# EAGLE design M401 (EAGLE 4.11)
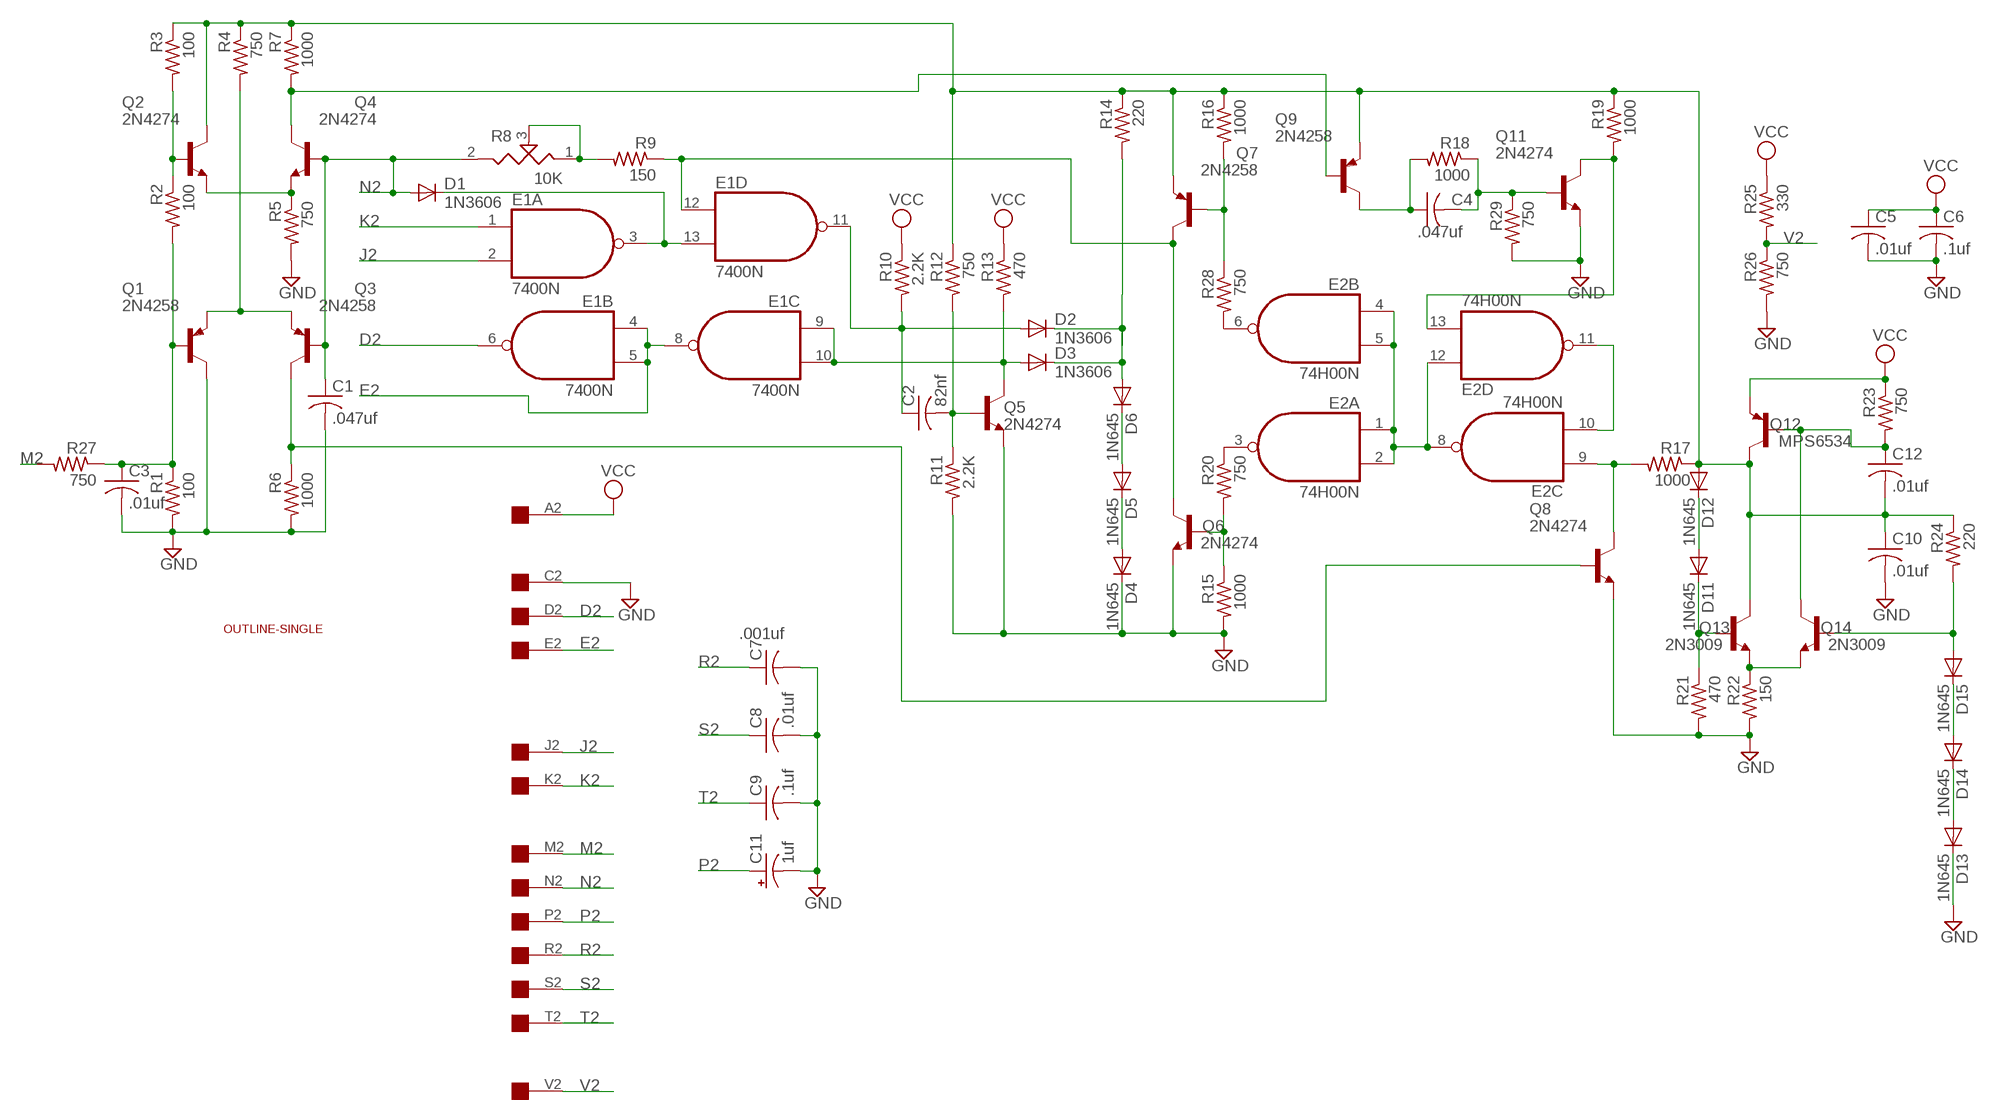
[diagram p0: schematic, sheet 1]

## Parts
C1  .047uf  C-US050-025X075  [C050-025X075]
C2  82nf  C-US050-025X075  [C050-025X075]
C3  .01uf  C-US050-025X075  [C050-025X075]
C4  .047uf  C-US050-025X075  [C050-025X075]
C5  .01uf  C-US050-025X075  [C050-025X075]
C6  .1uf  C-US050-025X075  [C050-025X075]
C7  .001uf  C-US050-025X075  [C050-025X075]
C8  .01uf  C-US050-025X075  [C050-025X075]
C9  .1uf  C-US050-025X075  [C050-025X075]
C10  .01uf  C-US050-025X075  [C050-025X075]
C11  1uf  CPOL-USE15-5AXIAL  [E15-5]
C12  .01uf  C-US050-025X075  [C050-025X075]
D1  1N3606  1N4148  [DO35-10]
D2  1N3606  1N4148  [DO35-10]
D3  1N3606  1N4148  [DO35-10]
D4  1N645  1N4148  [DO35-10]
D5  1N645  1N4148  [DO35-10]
D6  1N645  1N4148  [DO35-10]
D11  1N645  1N4148  [DO35-10]
D12  1N645  1N4148  [DO35-10]
D13  1N645  1N4148  [DO35-10]
D14  1N645  1N4148  [DO35-10]
D15  1N645  1N4148  [DO35-10]
E1  7400N  [DIL14]
E2  74H00N  7400N  [DIL14]
Q1  2N4258  2N3637-PNP-TO39-EBC  [TO39]
Q2  2N4274  2N3019-NPN-TO39-EBC  [TO39]
Q3  2N4258  2N3637-PNP-TO39-EBC  [TO39]
Q4  2N4274  2N3019-NPN-TO39-EBC  [TO39]
Q5  2N4274  2N3019-NPN-TO39-EBC  [TO39]
Q6  2N4274  2N3019-NPN-TO39-EBC  [TO39]
Q7  2N4258  2N3637-PNP-TO39-EBC  [TO39]
Q8  2N4274  2N3019-NPN-TO39-EBC  [TO39]
Q9  2N4258  2N3637-PNP-TO39-EBC  [TO39]
Q11  2N4274  2N3019-NPN-TO39-EBC  [TO39]
Q12  MPS6534  2N3637-PNP-TO39-EBC  [TO39]
Q13  2N3009  2N3019-NPN-TO39-EBC  [TO39]
Q14  2N3009  2N3019-NPN-TO39-EBC  [TO39]
R1  100  R-US_0207/10  [0207/10]
R2  100  R-US_0207/10  [0207/10]
R3  100  R-US_0207/10  [0207/10]
R4  750  R-US_0207/10  [0207/10]
R5  750  R-US_0207/10  [0207/10]
R6  1000  R-US_0207/10  [0207/10]
R7  1000  R-US_0207/10  [0207/10]
R8  10K  POTUS-TRIM  [PT-SPIN]
R9  150  R-US_0207/10  [0207/10]
R10  2.2K  R-US_0207/10  [0207/10]
R11  2.2K  R-US_0207/10  [0207/10]
R12  750  R-US_0207/10  [0207/10]
R13  470  R-US_0207/10  [0207/10]
R14  220  R-US_0207/10  [0207/10]
R15  1000  R-US_0207/10  [0207/10]
R16  1000  R-US_0207/10  [0207/10]
R17  1000  R-US_0207/10  [0207/10]
R18  1000  R-US_0207/10  [0207/10]
R19  1000  R-US_0207/10  [0207/10]
R20  750  R-US_0207/10  [0207/10]
R21  470  R-US_0207/10  [0207/10]
R22  150  R-US_0207/10  [0207/10]
R23  750  R-US_0207/10  [0207/10]
R24  220  R-US_0207/10  [0207/10]
R25  330  R-US_0207/10  [0207/10]
R26  750  R-US_0207/10  [0207/10]
R27  750  R-US_0207/10  [0207/10]
R28  750  R-US_0207/10  [0207/10]
R29  750  R-US_0207/10  [0207/10]
U$1  OUTLINE-SINGLE  [SINGLE]
U$2  EDGE-1  [EDGE-CON1]

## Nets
D2: E1.6(B:O) U$2.D2
E2: E1.4(B:I0) E1.5(B:I1) E1.8(C:O) U$2.E2
GND [power]: C1.2 C3.2 C5.2 C6.2 C7.2 C8.2 C9.2 C10.2 C11.- D4.C D13.C Q1.3(C) Q5.1(E) Q6.1(E) Q8.1(E) Q11.1(E) R1.2 R5.2 R6.2 R11.2 R15.2 R21.2 R22.2 R26.2 R29.2 U$2.C2
J2: E1.2(A:I1) U$2.J2
K2: E1.1(A:I0) U$2.K2
M2: R27.2 U$2.M2
N2: C1.1 D1.A Q3.2(B) Q4.2(B) R8.2 U$2.N2
N$1: D14.A D15.C
N$2: D13.A D14.C
N$3: D15.A Q14.2(B) R24.2
N$4: C12.1 Q12.2(B) Q14.3(C) R23.2
N$5: C10.1 C12.2 D12.A Q2.3(C) Q7.1(E) Q9.1(E) Q12.3(C) Q13.3(C) R3.1 R4.1 R7.1 R12.1 R14.1 R16.1 R17.1 R19.1 R24.1
N$6: D11.C Q13.2(B) R21.1
N$7 [power]: Q13.1(E) Q14.1(E) R22.1
N$8: D11.A D12.C
N$9: E2.1(A:I0) E2.2(A:I1) E2.4(B:I0) E2.5(B:I1) E2.8(C:O) E2.12(D:I0)
N$10: C3.1 Q1.2(B) R1.1 R2.2 R27.1
N$11: D3.A E1.9(C:I0) E1.10(C:I1) Q5.3(C) R13.2
N$12: D1.C E1.3(A:O) E1.13(D:I1)
N$13: D4.A D5.C
N$14: E2.10(C:I1) E2.11(D:O)
N$15: E2.9(C:I0) Q8.3(C) R17.2
N$16: E2.3(A:O) R20.1
N$17: E2.6(B:O) R28.2
N$18: Q7.2(B) R16.2 R28.1
N$19: Q6.2(B) R15.1 R20.2
N$20: D5.A D6.C
N$21: E1.12(D:I0) Q6.3(C) Q7.3(C) R9.1
N$22: C4.1 Q9.3(C) R18.2
N$23: C4.2 Q11.2(B) R18.1 R29.1
N$24: E2.13(D:I1) Q11.3(C) R19.2
N$25: D2.C D3.C D6.A R14.2
N$26: R8.1 R8.3 R9.2
N$28: C2.2 Q5.2(B) R11.1 R12.2
N$29: Q3.3(C) Q8.2(B) R6.1
N$30: C2.1 D2.A E1.11(D:O) R10.2
N$32: Q1.1(E) Q3.1(E) R4.2
N$33: Q4.3(C) Q9.2(B) R7.2
N$34: Q2.2(B) R2.1 R3.2
N$35: Q2.1(E) Q4.1(E) R5.1
P2: C11.+ U$2.P2
R2: C7.1 U$2.R2
S2: C8.1 U$2.S2
T2: C9.1 U$2.T2
V2: R25.2 R26.1 U$2.V2
VCC [power]: C5.1 C6.1 Q12.1(E) R10.1 R13.1 R23.1 R25.1 U$2.A2
Unconnected: U$2.B2 U$2.F2 U$2.H2 U$2.L2 U$2.U2

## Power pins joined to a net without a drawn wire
GND: E1.7(P:GND) E2.7(P:GND)
VCC: E1.14(P:VCC) E2.14(P:VCC)

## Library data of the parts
C1-C10 C12 = rcl:C-US: CAPACITOR, American symbol
C11 = rcl:CPOL-US: POLARIZED CAPACITOR, American symbol
D1-D6 D11-D15 = diode:1N4148: DIODE
E1 E2 = 74xx-us:74*00: Quad 2-input NAND gate
Q1 Q3 Q7 Q9 Q12 = transistor:*-PNP-: PNP Transistror
Q2 Q4-Q6 Q8 Q11 Q13 Q14 = transistor:*-NPN-: NPN Transistror
R1-R7 R9-R29 = rcl:R-US_: RESISTOR, American symbol
R8 = discrete:POTUS-TRIM
U$1 = dec-con:OUTLINE-*: Board outlines for DEC boards.
U$2 = dec-con:EDGE-1: Single-Sided DEC Edge Connector -- (side 2)

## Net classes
1 power: width 0.508 mm, drill 0.508 mm

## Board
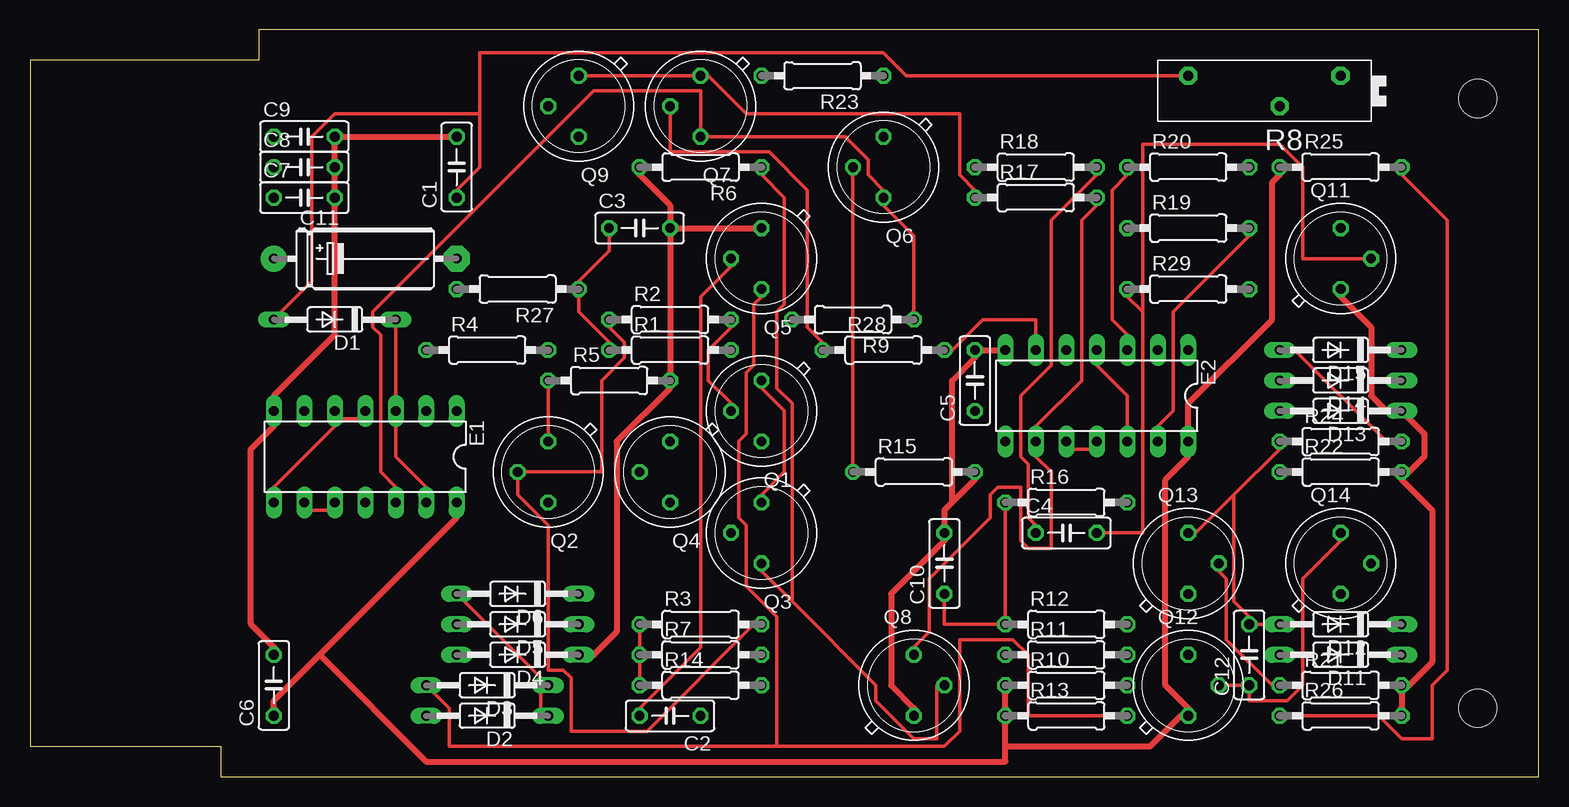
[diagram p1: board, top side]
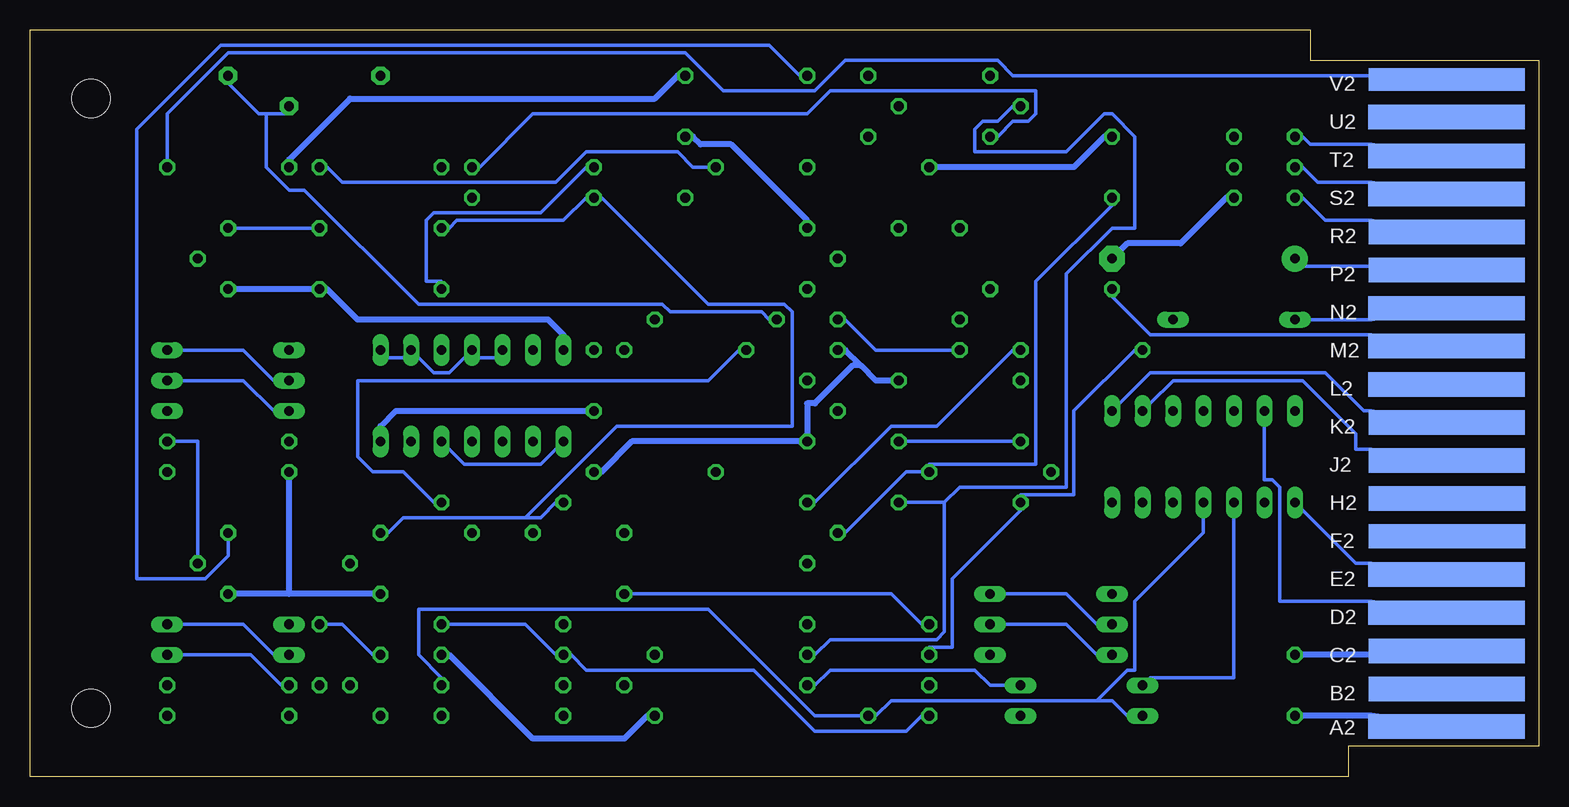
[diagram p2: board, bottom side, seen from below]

Size 125.73 x 62.23 mm. Coordinates in mm from the lower left corner, seen from the top.
Copper layers (1*16): Top 0.035mm / dielectric 1.5mm / Bottom 0.035mm
Design rules "10mils": minimum track width 12mil, minimum drill 28mil, track to track 10mil, track to pad 10mil, pad to pad 10mil, via to via 10mil, smd to smd 10mil, copper to edge 25mil, drill to drill 10mil, minimum pad ring 10mil, minimum via ring 8mil, stop-mask expansion 0mil, vias tented up to drill 0mil, thermal gap 10mil

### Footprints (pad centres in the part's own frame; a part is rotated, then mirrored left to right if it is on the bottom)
C050-025X075 = drill 0.813 octagon: 1 -2.54,0; 2 2.54,0
E15-5 = drill 0.813 pad 2.159 round: + -7.62,0 | drill 0.813 pad 2.159 octagon: - 7.62,0
DO35-10 = drill 0.813 long: A 5.08,0; C -5.08,0
DIL14 = drill 0.813 long: 1 -7.62,-3.81; 2 -5.08,-3.81; 3 -2.54,-3.81; 4 0,-3.81; 5 2.54,-3.81; 6 5.08,-3.81; 7 7.62,-3.81; 8 7.62,3.81; 9 5.08,3.81; 10 2.54,3.81; 11 0,3.81; 12 -2.54,3.81; 13 -5.08,3.81; 14 -7.62,3.81
TO39 = drill 0.813 octagon: 1 0,-2.54; 2 2.54,0; 3 0,2.54
0207/10 = drill 0.813 octagon: 1 -5.08,0; 2 5.08,0
PT-SPIN = drill 0.813 pad 1.524 octagon: 1 -6.35,-1.27; 2 6.35,-1.27; 3 -1.27,1.27
SINGLE = hole 3.175: 120.65,56.515; 120.65,5.715
EDGE-CON1 = smd 13.017 x 2.032 bottom: A2 7.69,4.194; B2 7.668,7.328; C2 7.668,10.49; D2 7.693,13.665; E2 7.693,16.84; F2 7.642,20.041; H2 7.642,23.19; J2 7.668,26.34; K2 7.668,29.515; L2 7.693,32.69; M2 7.693,35.89; N2 7.693,39.04; P2 7.668,42.24; R2 7.668,45.39; S2 7.693,48.565; T2 7.693,51.74; U2 7.693,54.966 | smd 13.017 x 1.905 bottom: V2 7.668,58.102

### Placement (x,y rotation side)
C1  35.56,50.8 90 top
C2  53.34,5.08 180 top
C3  50.8,45.72 0 top
C4  86.36,20.32 0 top
C5  78.74,33.02 90 top
C6  20.32,7.62 90 top
C7  22.86,48.26 0 top
C8  22.86,50.8 0 top
C9  22.86,53.34 0 top
C10  76.2,17.78 90 top
C11  27.94,43.18 0 top
C12  101.6,10.16 90 top
D1  25.4,38.1 180 top
D2  38.1,5.08 180 top
D3  38.1,7.62 180 top
D4  40.64,10.16 180 top
D5  40.64,12.7 180 top
D6  40.64,15.24 180 top
D11  109.22,10.16 180 top
D12  109.22,12.7 180 top
D13  109.22,30.48 180 top
D14  109.22,33.02 180 top
D15  109.22,35.56 180 top
E1  27.94,26.67 180 top
E2  88.9,31.75 180 top
Q1  60.96,30.48 180 top
Q2  43.18,25.4 180 top
Q3  60.96,20.32 180 top
Q4  53.34,25.4 180 top
Q5  60.96,43.18 180 top
Q6  71.12,50.8 180 top
Q7  55.88,55.88 180 top
Q8  73.66,7.62 0 top
Q9  45.72,55.88 180 top
Q11  109.22,43.18 0 top
Q12  96.52,7.62 0 top
Q13  96.52,17.78 0 top
Q14  109.22,17.78 0 top
R1  53.34,35.56 0 top
R2  53.34,38.1 0 top
R3  55.88,12.7 0 top
R4  38.1,35.56 0 top
R5  48.26,33.02 0 top
R6  55.88,50.8 180 top
R7  55.88,10.16 0 top
R8  102.87,57.15 180 top
R9  68.58,38.1 180 top
R10  86.36,7.62 0 top
R11  86.36,10.16 0 top
R12  86.36,12.7 0 top
R13  86.36,5.08 0 top
R14  55.88,7.62 0 top
R15  73.66,25.4 0 top
R16  86.36,22.86 0 top
R17  83.82,48.26 0 top
R18  83.82,50.8 0 top
R19  96.52,45.72 0 top
R20  96.52,50.8 0 top
R21  109.22,7.62 0 top
R22  109.22,25.4 0 top
R23  66.04,58.42 180 top
R24  109.22,27.94 0 top
R25  109.22,50.8 0 top
R26  109.22,5.08 0 top
R27  40.64,40.64 180 top
R28  71.12,35.56 0 top
R29  96.52,40.64 0 top
U$1  0,0 0 top
U$2  0,0 0 top

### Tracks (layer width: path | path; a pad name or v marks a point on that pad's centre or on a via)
D2
  Bottom 0.305: E1.6 22.86,29.21 22.86,24.77 22.23,24.77 21.59,24.13 21.59,14.61 13.97,14.61 U$2.D2
E2
  Top 0.305: E1.8 20.32,24.13 25.4,29.21 E1.5 26.04,29.84 27.31,29.84 E1.4
  Bottom 0.305: E1.8 19.69,22.23 15.24,17.78 13.97,17.78 U$2.E2
GND
  Top 0.508: C1.2 34.93,53.34 26.04,53.34 C9.2 25.4,52.7 25.4,51.44 C8.2 25.4,50.16 25.4,48.9 C7.2 25.4,47.62 25.4,36.83 20.32,31.75 E1.7 20.32,29.21 18.42,27.3 18.42,12.7 20.32,10.79 C6.2 | R26.2 114.3,5.71 114.3,6.99 R21.2 114.94,7.62 116.84,9.53 116.84,22.23 114.3,24.77 R22.2 114.94,25.4 116.21,26.67 116.21,28.57 114.94,29.84 D13.C 113.03,30.48 111.76,31.75 111.76,37.47 109.22,40.01 Q11.1 | E2.7 80.65,35.56 79.38,35.56 C5.2 78.74,34.92 76.84,33.02 76.84,22.86 | Q8.1 73.66,5.71 71.76,7.62 71.76,15.24 76.2,19.68 C10.2 76.2,20.95 76.2,22.23 76.84,22.86 | 76.84,22.86 78.74,24.77 R15.2 | R6.2 50.8,50.16 53.34,47.62 53.34,46.35 C3.2 | Q5.1 60.33,45.72 53.98,45.72 C3.2 | D4.C 46.99,10.16 48.9,12.06 48.9,27.94 53.34,32.38 R5.2 53.34,33.66 53.34,45.09 C3.2
  Bottom 0.508: C6.2 19.69,10.16 13.97,10.16 U$2.C2 | C11.- 34.93,43.81 34.29,44.45 29.85,44.45 26.04,48.26 C7.2 | Q11.1 108.59,40.64 102.24,40.64 R29.2 100.97,40.64 98.43,38.1 82.55,38.1 81.28,36.83 E2.7 | R11.2 90.81,10.16 83.82,3.17 76.2,3.17 74.3,5.08 Q8.1 | Q6.1 70.49,53.34 69.85,52.7 67.31,52.7 60.96,46.35 Q5.1 | 56.52,34.29 55.25,33.02 53.98,33.02 R5.2 | 56.52,34.29 57.79,35.56 R1.2 | 56.52,34.29 57.15,34.29 60.33,31.11 60.96,31.11 60.96,28.57 Q1.3 61.6,27.94 75.57,27.94 78.11,25.4 R15.2 | C1.2 36.2,53.34 38.74,50.8 50.17,50.8 R6.2
J2
  Bottom 0.305: E1.2 32.39,31.11 30.48,33.02 19.69,33.02 15.24,28.57 15.24,27.3 13.97,27.3 U$2.J2
K2
  Bottom 0.305: E1.1 34.93,31.11 32.39,33.66 17.78,33.66 14.61,30.48 13.97,30.48 U$2.K2
M2
  Bottom 0.305: R27.2 35.56,40.01 32.39,36.83 13.97,36.83 U$2.M2
N2
  Top 0.305: 37.47,55.24 37.47,50.8 35.56,48.9 C1.1 | 37.47,55.24 37.47,60.33 71.12,60.33 73.03,58.42 95.89,58.42 R8.2 | 37.47,55.24 25.4,55.24 23.5,53.34 23.5,41.27 20.96,38.73 D1.A
  Bottom 0.305: D1.A 19.05,38.1 13.97,38.1 U$2.N2 | Q3.2 57.79,20.32 52.71,25.4 51.44,25.4 Q4.2 50.8,26.04 41.91,26.04 41.91,41.27 35.56,47.62 C1.1
N$1
  Bottom 0.305: D14.A 105.41,33.02 107.95,35.56 113.03,35.56 D15.C
N$2
  Bottom 0.305: D13.A 105.41,30.48 107.95,33.02 113.03,33.02 D14.C
N$3
  Top 0.305: D15.A 105.41,35.56 113.03,27.94 113.67,27.94 R24.2
  Bottom 0.305: Q14.2 111.76,18.41 111.76,27.94 113.67,27.94 R24.2
N$4
  Top 0.305: Q12.2 99.7,7.62 100.97,7.62 C12.1 101.6,6.99 101.6,6.35 104.78,6.35 106.05,7.62 106.05,16.51 109.22,19.68 Q14.3
  Bottom 0.305: R23.2 61.6,58.42 64.14,60.96 109.86,60.96 116.84,53.98 116.84,16.51 111.13,16.51 109.22,18.41 109.22,19.68 Q14.3
N$5
  Top 0.305: Q9.1 46.36,58.42 55.25,58.42 Q7.1 56.52,58.42 59.69,55.24 77.47,55.24 77.47,50.16 78.74,48.9 R17.1 | R14.1 50.8,8.26 50.8,9.53 R7.1 50.8,10.79 50.8,12.06 R3.1 | C10.1 76.2,14.61 76.2,12.7 80.65,12.7 R12.1 81.28,13.34 81.28,22.23 R16.1 | D12.A 102.87,12.7 102.24,12.7 C12.2 101.6,13.34 100.33,14.61 100.33,23.5 | 100.33,23.5 104.14,27.3 R24.1 | 100.33,23.5 97.16,20.32 Q13.3
  Bottom 0.305: R19.1 90.81,45.72 90.17,46.35 81.28,46.35 79.38,48.26 R17.1 78.11,48.26 69.22,39.37 62.87,39.37 62.23,38.73 62.23,29.21 76.84,29.21 84.46,21.59 | R7.1 50.8,10.79 48.9,10.79 48.9,16.51 43.18,22.23 Q2.3 43.18,23.5 38.74,23.5 38.74,30.48 33.66,35.56 R4.1 | Q12.3 97.16,10.16 99.7,12.7 100.97,12.7 C12.2 | 84.46,21.59 94.62,21.59 95.89,20.32 Q13.3 | 84.46,21.59 83.19,21.59 81.92,22.86 R16.1 | R3.1 51.44,12.7 53.98,15.24 75.57,15.24 C10.1
N$6
  Top 0.305: Q13.2 99.06,17.14 99.7,16.51 99.7,11.43 103.51,7.62 R21.1
  Bottom 0.305: R21.1 104.78,7.62 107.32,10.16 113.03,10.16 D11.C
N$7
  Bottom 0.508: 104.14,15.24 108.59,15.24 Q14.1 | 104.14,15.24 97.16,15.24 Q13.1 | 104.14,15.24 104.14,24.77 R22.1
N$8
  Bottom 0.305: D11.A 105.41,10.16 107.95,12.7 113.03,12.7 D12.C
N$9
  Top 0.305: E2.4 88.9,34.29 91.44,31.75 91.44,29.21 E2.12
  Bottom 0.305: E2.1 95.89,34.92 94.62,34.92 E2.2 93.35,34.92 92.08,33.66 90.81,33.66 89.54,34.92 E2.4 88.27,34.92 87,34.92 E2.5 | E2.8 81.92,27.3 83.19,26.04 89.54,26.04 90.81,27.3 E2.12
N$10
  Top 0.305: Q1.2 58.42,31.11 56.52,33.02 56.52,35.56 58.42,37.47 R2.2 | C3.1 48.26,45.09 48.26,43.81 45.72,41.27 R27.1 45.72,40.01 45.72,38.73 48.26,36.2 R1.1
  Bottom 0.305: R2.2 57.79,38.1 55.25,35.56 48.9,35.56 R1.1
N$11
  Top 0.305: E1.9 23.5,22.23 24.77,22.23 E1.10 | 62.23,2.54 34.93,2.54 34.93,5.71 33.66,6.99 D3.A | 62.23,2.54 76.2,2.54 77.47,3.81 77.47,11.43 81.92,11.43 83.19,10.16 83.19,5.08 90.81,5.08 R13.2 | 62.23,2.54 62.23,13.34 59.69,15.88 59.69,20.95 59.06,21.59 59.06,27.94 59.69,28.57 59.69,33.66 60.33,34.29 60.33,39.37 60.96,40.01 Q5.3
  Bottom 0.305: E1.10 25.4,21.59 25.4,8.26 32.39,8.26 D3.A
N$12
  Top 0.305: D1.C 30.48,37.47 30.48,31.75 E1.3 30.48,29.21 30.48,26.67 33.02,24.13 E1.13
N$13
  Bottom 0.305: D4.A 36.83,10.16 39.37,12.7 44.45,12.7 D5.C
N$14
  Top 0.305: E2.10 87,27.3 88.27,27.3 E2.11
N$15
  Top 0.305: Q8.3 73.66,10.79 74.93,12.06 74.93,16.51 80.01,21.59 80.01,23.5 80.65,24.13 82.55,24.13 82.55,19.68 83.19,19.05 85.09,19.05 85.09,25.4 83.82,26.67 E2.9 83.82,29.21 87.63,33.02 87.63,46.35 88.9,47.62 R17.2
N$16
  Top 0.305: E2.3 91.44,36.83 90.17,38.1 90.17,48.9 91.44,50.16 R20.1
N$17
  Top 0.305: R28.2 76.84,35.56 79.38,38.1 83.82,38.1 83.82,36.83 E2.6
N$18
  Top 0.305: R28.1 66.04,36.2 64.77,37.47 64.77,48.9 61.6,52.07 53.34,52.07 53.34,55.24 Q7.2
  Bottom 0.305: R16.2 92.08,22.86 94.62,25.4 97.16,25.4 98.43,26.67 98.43,33.02 69.22,33.02 66.68,35.56 R28.1
N$19
  Top 0.305: R15.1 68.58,26.04 68.58,50.16 Q6.2
  Bottom 0.305: R20.2 100.97,50.8 99.7,49.53 81.92,49.53 79.38,52.07 71.76,52.07 70.49,50.8 69.22,50.8 Q6.2
N$20
  Bottom 0.305: D5.A 36.83,12.7 39.37,15.24 44.45,15.24 D6.C
N$21
  Top 0.305: R9.1 73.66,38.73 73.66,45.09 71.12,47.62 Q6.3 71.12,48.9 69.85,50.16 69.85,51.44 67.95,53.34 56.52,53.34 Q7.3 55.88,53.98 55.88,57.15 46.99,57.15 28.58,38.73 28.58,37.47 29.21,36.83 29.21,25.4 30.48,24.13 E1.12
N$22
  Top 0.305: C4.1 83.82,20.95 83.19,21.59 83.19,26.04 82.55,26.67 82.55,31.75 85.09,34.29 85.09,46.35 88.9,50.16 R18.2
  Bottom 0.305: Q9.3 45.09,53.34 43.82,54.61 42.55,54.61 41.91,55.24 41.91,57.15 59.06,57.15 60.96,55.24 83.82,55.24 88.27,50.8 R18.2
N$23
  Top 0.305: 92.71,38.73 92.71,20.32 89.54,20.32 C4.2 | 92.71,38.73 91.44,40.01 R29.1 | 92.71,38.73 92.71,52.7 104.14,52.7 106.05,50.8 106.05,43.18 111.13,43.18 Q11.2
  Bottom 0.305: R18.1 79.38,50.8 83.19,46.99 92.08,46.99 92.71,46.35 92.71,41.27 91.44,41.27 R29.1
N$24
  Top 0.305: E2.13 93.98,29.21 95.25,30.48 95.25,38.73 101.6,45.09 R19.2
  Bottom 0.305: Q11.3 108.59,45.72 102.24,45.72 R19.2
N$25
  Top 0.305: D2.C 42.55,5.71 42.55,6.99 D3.C 42.55,8.26 36.2,14.61 D6.A
  Bottom 0.305: R14.2 60.33,7.62 59.06,8.89 46.99,8.89 45.72,7.62 44.45,7.62 D3.C
N$26
  Bottom 0.305: 106.05,55.24 106.05,50.8 104.14,48.9 102.87,48.9 93.35,39.37 73.03,39.37 72.39,38.73 64.77,38.73 64.14,38.1 R9.2 | 106.05,55.24 104.14,55.24 R8.3 | 106.05,55.24 106.68,55.24 109.22,57.78 R8.1
N$28
  Top 0.305: C2.2 50.8,5.71 55.88,10.79 55.88,40.01 58.42,42.55 Q5.2
  Bottom 0.305: R12.2 90.81,12.7 84.46,12.7 81.92,10.16 R11.1 80.65,10.16 79.38,8.89 65.41,8.89 60.33,3.81 52.71,3.81 51.44,5.08 C2.2
N$29
  Top 0.305: 63.5,14.61 70.49,7.62 70.49,6.35 73.66,3.17 75.57,3.17 75.57,7.62 Q8.2 | 63.5,14.61 60.96,17.14 Q3.3 | 63.5,14.61 63.5,31.11 62.23,32.38 62.23,38.73 62.87,39.37 62.87,48.26 60.96,50.16 R6.1
N$30
  Bottom 0.305: 36.83,6.35 53.98,6.35 55.25,5.08 C2.1 56.52,5.08 60.33,5.08 69.22,13.97 93.35,13.97 93.35,10.16 91.44,8.26 R10.2 | 36.83,6.35 35.56,6.35 34.29,5.08 D2.A | 36.83,6.35 34.29,8.89 33.66,8.89 33.66,14.61 27.94,20.32 27.94,21.59 E1.11
N$32
  Top 0.305: Q3.1 60.96,23.5 62.87,25.4 62.87,30.48 60.96,32.38 Q1.1
  Bottom 0.305: R4.2 43.82,35.56 50.17,29.21 53.98,29.21 60.33,22.86 Q3.1
N$33
  Bottom 0.305: 49.53,22.86 49.53,12.06 50.17,11.43 59.06,11.43 60.33,10.16 R7.2 | 49.53,22.86 52.71,22.86 Q4.3 | 49.53,22.86 48.26,24.13 39.37,24.13 39.37,41.91 35.56,45.72 33.66,45.72 33.66,53.34 35.56,55.24 36.2,55.24 39.37,52.07 46.99,52.07 46.99,53.98 46.36,54.61 45.09,54.61 43.82,55.88 Q9.2
N$34
  Top 0.305: R2.1 48.26,37.47 49.53,36.2 49.53,34.92 47.63,33.02 47.63,25.4 41.28,25.4 Q2.2 40.64,24.77 40.64,23.5 43.18,20.95 43.18,8.89 44.45,8.89 45.09,8.26 45.09,3.81 51.44,3.81 60.33,12.7 R3.2
N$35
  Top 0.305: Q2.1 43.18,28.57 43.18,32.38 R5.1
  Bottom 0.305: Q4.1 52.71,27.94 43.82,27.94 Q2.1
P2
  Bottom 0.305: C11.+ 19.69,42.55 13.97,42.55 U$2.P2
R2
  Bottom 0.305: C7.1 19.69,48.26 17.78,46.35 13.97,46.35 U$2.R2
S2
  Bottom 0.305: C8.1 19.69,50.8 18.42,49.53 13.97,49.53 U$2.S2
T2
  Bottom 0.305: C9.1 19.69,53.34 19.05,52.7 13.97,52.7 U$2.T2
V2
  Top 0.305: R26.1 104.78,5.08 112.4,5.08 114.3,3.17 116.84,3.17 116.84,7.62 118.11,8.89 118.11,46.35 114.3,50.16 R25.2
  Bottom 0.305: U$2.V2 13.97,58.42 43.82,58.42 45.09,59.69 57.79,59.69 60.33,57.15 67.95,57.15 71.12,60.33 109.22,60.33 114.3,55.24 114.3,51.44 R25.2
VCC
  Top 0.508: 24.13,10.16 20.32,6.35 20.32,5.71 C6.1 | 24.13,10.16 35.56,21.59 E1.14 | R10.1 81.28,6.99 81.28,5.71 R13.1 81.28,4.45 81.28,2.54 | 81.28,2.54 93.35,2.54 95.89,5.08 Q12.1 96.52,5.71 94.62,7.62 94.62,24.77 96.52,26.67 E2.14 96.52,29.21 96.52,31.11 103.51,38.1 103.51,49.53 104.14,50.16 R25.1 | 24.13,10.16 33.02,1.27 81.28,1.27 81.28,2.54
  Bottom 0.508: C6.1 19.69,5.08 13.97,5.08 U$2.A2 | E2.14 96.52,29.21 95.25,30.48 79.38,30.48 C5.1 | R23.1 71.76,58.42 73.66,56.52 99.06,56.52 104.14,51.44 R25.1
